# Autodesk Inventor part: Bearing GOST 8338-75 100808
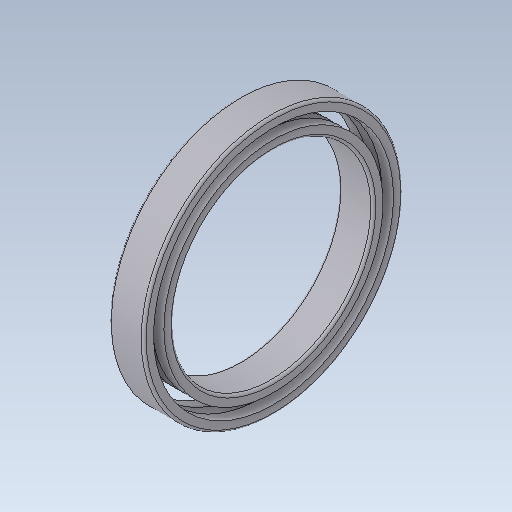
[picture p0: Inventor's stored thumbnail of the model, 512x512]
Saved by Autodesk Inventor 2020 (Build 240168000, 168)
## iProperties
Created: 2017-09
Part Number: Bearing GOST 8338-75 100808
Material: Ogólny
Document SubType Name: Modeling
Designer: Tomasz
Density: 1 g/cm^3
Appearance: Domyślna
Sending System: SolidWorks 2017
Last Author: Tomasz
Last Saved: 2017-09-17
Source: Bearing GOST 8338-75 100808_1
Author: Tomasz
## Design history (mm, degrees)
fillet "Fillet3"
fillet "Fillet1"
fillet "Ball"
node "Bryła1"
node "Bryła2"
node "Bryła3"
